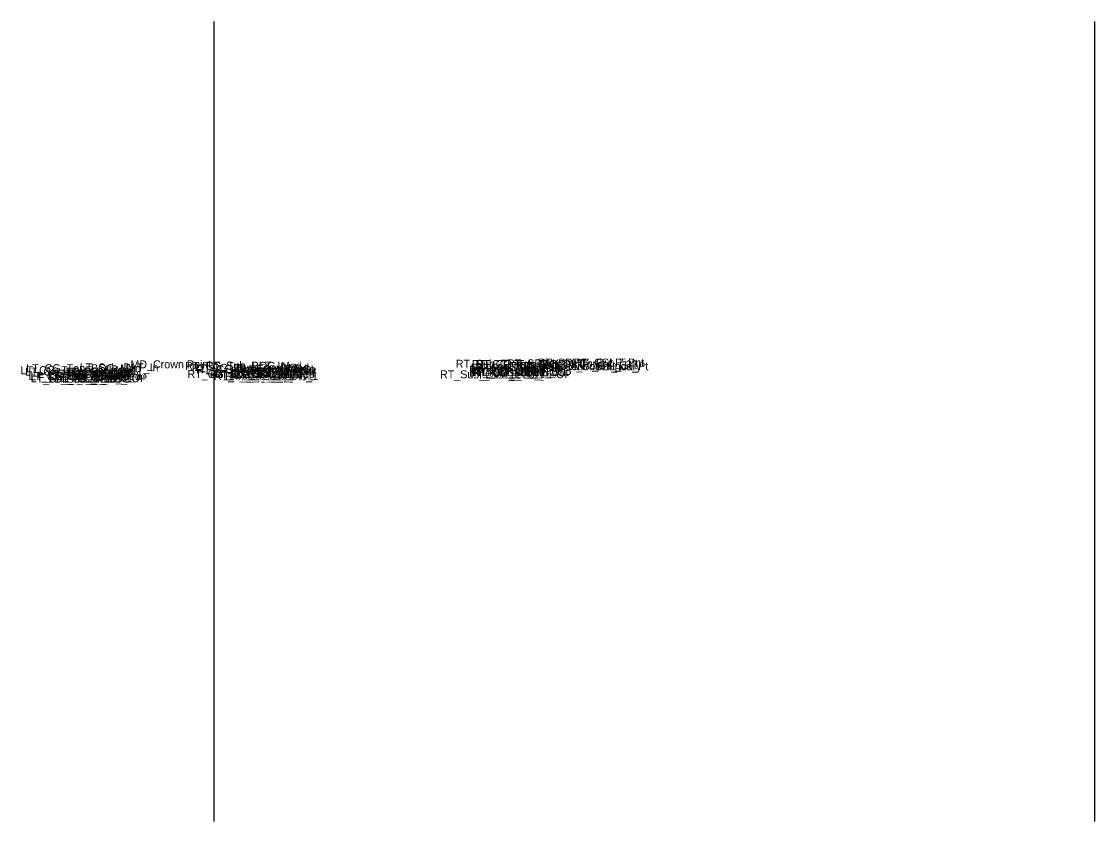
# Model space of a CAD drawing. Extents: x 0 to 6300, y -50 to 9550.
# Drawn here: x 2126 to 2260, y 7950 to 8050 of the extents above; entities that cross this region are included whole.
import ezdxf

# ---------------------------------------------------------------- set-up
doc = ezdxf.new("R2010")
doc.units = 0
for name, color, linetype in [('Default', 7, 'Continuous'), ('Prop XS Exc Vertical Line 2', 7, 'Continuous'), ('Prop XS Exc Vertical Line 3', 7, 'Continuous')]:
    doc.layers.add(name, color=color, linetype=linetype)

msp = doc.modelspace()

# ---------------------------------------------------------------- linework, layer by layer
at = {"layer": 'Prop XS Exc Vertical Line 2'}
msp.add_line((2150, 8050), (2150, 7950), dxfattribs=at)
at = {"layer": 'Prop XS Exc Vertical Line 3'}
msp.add_line((2260, 8050), (2260, 7950), dxfattribs=at)

# ---------------------------------------------------------------- texts
at = {"layer": 'Default'}
for s, p in [('LT_CG_Top_Face_Med', (2125.87, 8005.91)), ('LT_CG_Top_Gut_Med', (2126.42, 8005.74)), ('LT_CG_Top_BOC_Med', (2126.57, 8006.16)), ('LT_PV1_PGL', (2131.5, 8005.73)), ('LT_Sub_DLT_In', (2133.28, 8006.26)), ('MD_Crown Point', (2139.58, 8006.65)), ('RT_CG_Top_BOC_Med', (2146.43, 8006.45)), ('RT_CG_Top_Face_Med', (2147.25, 8006.2)), ('RT_CG_Top_Gut_Med', (2147.8, 8006.03)), ('RT_Sub_DLT_In', (2149.02, 8006.49)), ('RT_PV2_OEEOP', (2152.17, 8005.78)), ('RT_PV2_IEEOP', (2152.93, 8005.78)), ('RT_PV2_PGL', (2154.15, 8005.78)), ('RT_PV1_PGL', (2154.38, 8006.03)), ('RT_Sub_Trench_Out_DLT', (2180.22, 8006.71)), ('RT_PV2_OEOT', (2181.87, 8005.98)), ('RT_PV3_OEOT', (2181.87, 8005.73)), ('RT_PV1_OEOT', (2182.11, 8006.23)), ('RT_CG_Top_Face', (2182.22, 8006.67)), ('RT_CG_Bot_IE', (2182.22, 8005.65)), ('RT_CG1_Shelf_Out', (2182.36, 8005.67)), ('RT_CG_Top_BOC', (2182.69, 8006.67)), ('RT_CG_Top_Gut', (2182.75, 8006.17)), ('RT_CG_Bot_BOC', (2182.97, 8005.67)), ('RT_SDWK_In_Top', (2186.62, 8006.76)), ('RT_SDWK_In_Bot', (2186.87, 8006.43)), ('RT_SDWK_Out_Top', (2190.46, 8006.86)), ('RT_SDWK_Out_Bot', (2190.71, 8006.53)), ('Exterior Boundary', (2192.71, 8006.41)), ('RT_CSLP_Pnt', (2194.98, 8006.86)), ('RT_Tie_Pt', (2197.87, 8006.41)), ('LT_CG_Bot_BOC_Med', (2126.85, 8005.17)), ('LT_CG_Bot_IE_Med', (2127.09, 8005.14)), ('LT_Sub_IEOT_CG_1', (2127.13, 8004.89)), ('LT_PV2_OEEOP', (2129.29, 8005.48)), ('LT_PV3_OEEOP', (2129.29, 8005.23)), ('LT_Sub_OEEOP', (2129.33, 8004.85)), ('LT_PV2_IEEOP', (2130.05, 8005.48)), ('LT_Sub_IEEOP', (2130.09, 8004.85)), ('LT_CG1_Shelf_In', (2130.71, 8005.18)), ('LT_PV2_PGL', (2131.26, 8005.48)), ('LT_Sub_PGL', (2131.31, 8004.85)), ('LT_Sub_IEOP', (2133.05, 8004.94)), ('RT_CG_Bot_BOC_Med', (2146.71, 8005.44)), ('RT_CG1_Shelf_In', (2149.57, 8005.44)), ('RT_CG_Bot_IE_Med', (2149.98, 8005.45)), ('RT_Sub_IEOT_CG_1', (2150.01, 8005.2)), ('RT_Sub_IEOP', (2151.41, 8005.19)), ('RT_PV3_OEEOP', (2152.17, 8005.53)), ('RT_Sub_OEEOP', (2152.21, 8005.16)), ('RT_Sub_IEEOP', (2152.97, 8005.16)), ('RT_Sub_PGL', (2154.19, 8005.16)), ('RT_Sub_OEOT_CG_1', (2178.25, 8005.4)), ('RT_Sub_OEOT', (2181.92, 8005.36)), ('RT_Sub_OEOP', (2185.16, 8005.42))]:
    msp.add_text(s, height=1, dxfattribs=at).set_placement(p)

doc.saveas('drawing.dxf')
